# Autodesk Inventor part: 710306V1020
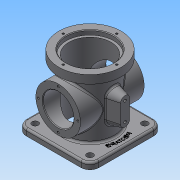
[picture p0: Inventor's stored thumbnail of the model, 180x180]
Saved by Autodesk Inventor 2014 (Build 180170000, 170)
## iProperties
Created: 2021-03
Part Number: 710306V1020
Material: 일반
Document SubType Name: Modeling
Designer: NET
Density: 1 g/cm^3
Appearance: 기본값
Author: NET
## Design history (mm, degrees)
sketch "스케치3"
  geometry: L1 (57, -57)-(-57, -57); L2 (-57, -57)-(-57, 57); L3 (-57, 57)-(57, 57); L4 (57, 57)-(57, -57); L5 (57, -57)-(-57, 57); L6 (-57, -57)-(57, 57); 1 further point
  constraints: 12 end point, 2 midpoint, 2 parallel, 1 horizontal, 1 perpendicular
  dimensions: "d5" = 114 distance of L2.end L3.end; "d6" = 114 distance of L1.end L2.end
extrude "돌출1" new body sketch "스케치3" distance "d7" = 10; taper "d8" = 0 deg
sketch "스케치4"
  geometry: C1 r 38 at (0, 0); 1 further point
  constraints: 1 centre point, 1 coincident
  dimensions: "d9" = 76 diameter of C1
extrude "돌출2" join sketch "스케치4" distance "d10" = 88; taper "d11" = 0 deg
sketch "스케치5"
  geometry: C1 r 38 at (0, 0) reference; C2 r 49 at (0, 0)
  constraints: 1 centre point, 1 coincident
  dimensions: "d12" = 98 diameter of C2
extrude "돌출3" join sketch "스케치5" distance "d13" = 13; taper "d14" = 0 deg
hole "구멍1" diameter "d17" = 74; stored, may be unused: countersink angle "d21" = 90 deg, drill point angle "d23" = 0 deg; dims "d18" = 6, "d19" = 4, "d20" = 2, "d22" = 7, "d98" = 10, "d99" = 10
hole "구멍2" diameter "d26" = 66; stored, may be unused: countersink angle "d30" = 90 deg, drill point angle "d32" = 0 deg; dims "d24" = 10, "d25" = 10, "d27" = 6, "d28" = 4, "d29" = 2, "d31" = 104
node "작업 평면1"
sketch "스케치6"
  geometry: L1 (57, 0)-(-57, 0) reference; C1 r 35 at (0, 54); 2 further points
  constraints: 1 centre point, 1 midpoint, 1 vertical alignment
  dimensions: "d34" = 70 diameter of C1; "d35" = 54 distance from line of C1.centre L1
extrude "돌출4" join sketch "스케치6" stored distance "d36" = 13; taper "d37" = 0 deg
hole "구멍3" diameter "d40" = 48; stored, may be unused: countersink angle "d44" = 90 deg, drill point angle "d46" = 0 deg; dims "d38" = 10, "d39" = 10, "d41" = 6, "d42" = 4, "d43" = 2, "d45" = 30
sketch "스케치7" dims "d47" = 62
  geometry: C1 r 24 at (0, 0) reference; C2 r 35 at (0, 0) reference; 3 further points
  constraints: 2 vertical alignment, 1 coincident, 2 other
hole "구멍4" sketch "스케치7" at (0, 31) diameter "d48" = 3.242; stored, may be unused: countersink angle "d52" = 90 deg, drill point angle "d54" = 118 deg; dims "d49" = 6, "d50" = 4, "d51" = 2, "d53" = 8
fillet "모깎기1" dims "d58" = 14
sketch "스케치8"
  geometry: A1 r 14 centre (-43, 43) between (-43, 57) and (-57, 43) reference; A2 r 14 centre (-43, -43) between (-57, -43) and (-43, -57) reference; A3 r 14 centre (43, -43) between (43, -57) and (57, -43) reference; A4 r 14 centre (43, 43) between (57, 43) and (43, 57) reference
hole "구멍5" sketch "스케치8" at (43, -43), (43, 43), (-43, 43), (-43, -43) diameter "d59" = 10; stored, may be unused: countersink angle "d63" = 90 deg, drill point angle "d65" = 118 deg; dims "d60" = 6, "d61" = 4, "d62" = 2, "d64" = 8
node "작업 평면2"
sketch "스케치9"
  geometry: L1 (0, 68.5)-(0, 39.5); L2 (7, 68.5)-(7, 39.5); L3 (-7, 39.5)-(-7, 68.5); L4 (43, 0)-(-43, 0) reference; A1 r 7 centre (0, 68.5) between (7, 68.5) and (-7, 68.5); A2 r 7 centre (0, 39.5) between (-7, 39.5) and (7, 39.5); 3 further points
  constraints: 8 end point, 4 point on circle, 4 tangent, 2 centre point, 2 midpoint, 1 parallel, 1 vertical, 1 vertical alignment
  dimensions: "d68" = 54 distance from line of L4 point (0, 54); "d69" = 14 distance between parallel lines of L2 L3; "d100" = 29 distance of L1.end L1.start
extrude "돌출5" join sketch "스케치9" stored distance "d71" = 13; taper "d72" = 15 deg
sketch "스케치10"
  geometry: A1 r 7 centre (-68.5, 0) between (-68.5, 7) and (-68.5, -7) reference; A2 r 7 centre (-39.5, 0) between (-39.5, -7) and (-39.5, 7) reference; 1 further point
hole "구멍6" sketch "스케치10" at (-68.5, 0), (-39.5, 0) diameter "d73" = 4.134; stored, may be unused: countersink angle "d77" = 90 deg, drill point angle "d79" = 118 deg; dims "d74" = 8, "d75" = 4, "d76" = 2, "d78" = 10
fillet "모깎기2" dims "d80" = 3
chamfer "모따기1" distance "d81" = 1; stored, may be unused: second distance "d82" = 2, angle "d83" = 45 deg
sketch "스케치11"
  geometry: C1 r 41 at (0, 0) reference; C2 r 50 at (0, 0)
  constraints: 1 centre point, 1 coincident, 1 other
  dimensions: "d84" = 100 diameter of C2
feature "엠보싱1" sketch "스케치11" dims "d5" = 114, "d6" = 114, "d85" = 0.5, "d86" = 0
sketch "스케치12" dims "d87" = 84
  geometry: C1 r 49 at (0, 0) reference; C2 r 38 at (0, 0) reference; 2 further points
  constraints: 2 horizontal alignment, 1 coincident, 2 other
hole "구멍7" sketch "스케치12" at (-42, 0) diameter "d88" = 3.242; stored, may be unused: countersink angle "d92" = 90 deg, drill point angle "d94" = 118 deg; dims "d89" = 6, "d90" = 4, "d91" = 2, "d93" = 8
node "솔리드1"
pattern_circular "원형 패턴1" dims angle "d56" = 360 deg
mirror "대칭1"
pattern_circular "원형 패턴2" dims angle "d96" = 360 deg
other parameters: "d66" = 55
